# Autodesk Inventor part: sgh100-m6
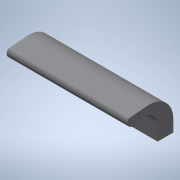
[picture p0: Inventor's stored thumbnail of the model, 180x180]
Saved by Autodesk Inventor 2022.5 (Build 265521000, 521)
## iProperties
Created: 2016-12
Part Number: sgh100-m6
Material: 一般
Document SubType Name: Modeling
Designer: imaocorp
Density: 1 g/cm^3
Appearance: 既定
Author: imaocorp
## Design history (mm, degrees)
node "sgh100-m6.x_t1"
node "sgh100-m6"
node "Base1"
